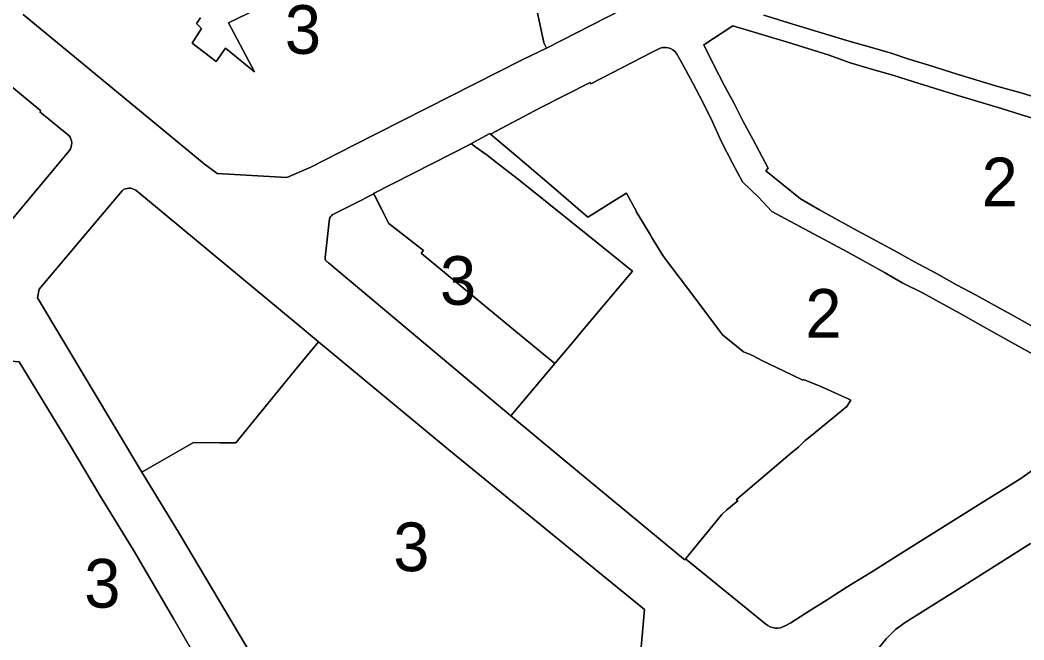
# Model space of a CAD drawing. Extents: x 598968 to 613553, y 4409678 to 4430833.
# Drawn here: x 607467.9 to 607715.2, y 4416082.8 to 4416235.4 of the extents above; entities that cross this region are included whole.
import ezdxf

# ---------------------------------------------------------------- set-up
doc = ezdxf.new("R2010")
doc.units = 0
for name, color, linetype in [('1', 7, 'Continuous'), ('ZONA 2. CARRERS DE CASES. Cases de trast', 7, 'Continuous'), ("ZONA 2_. CARRERS DE CASES. Afectades a ús d'aparcament", 7, 'Continuous'), ("ZONA 3. ILLES  D'EDIFICIS ENTRE MITGERES. EIXAMPLE.", 7, 'Continuous')]:
    doc.layers.add(name, color=color, linetype=linetype)

msp = doc.modelspace()

# ---------------------------------------------------------------- linework, layer by layer
at = {"layer": '1'}
for points in [[(607619.944, 4416239.9228), (607597.5985, 4416228.5216), (607591.5834, 4416225.5829), (607567.9956, 4416213.6341), (607550.1292, 4416204.571), (607539.5293, 4416199.2209), (607533.6794, 4416196.6108), (607516.4596, 4416197.5905), (607513.3096, 4416199.9804), (607468.71, 4416236.8092)], [(607721.2371, 4416215.4039), (607714.1772, 4416217.5738), (607708.7672, 4416219.0737), (607699.0273, 4416222.0135), (607691.7774, 4416224.2833), (607686.8275, 4416225.8132), (607682.4975, 4416227.2631), (607677.3976, 4416228.723), (607672.4376, 4416230.1329), (607667.2377, 4416231.7328), (607657.2478, 4416234.7326), (607651.1278, 4416236.6524)], [(607716.9073, 4416160.2145), (607712.1974, 4416162.8244), (607707.8974, 4416165.2243), (607703.4175, 4416167.6642), (607698.6075, 4416170.2441), (607693.6676, 4416172.9639), (607689.3276, 4416175.3138), (607686.6176, 4416176.7938), (607684.1576, 4416178.1337), (607678.9477, 4416180.9536), (607674.2277, 4416183.5435), (607669.4633, 4416186.1615), (607664.8593, 4416188.6726), (607660.1979, 4416191.4131), (607655.9179, 4416194.863), (607651.648, 4416198.2929), (607652.2368, 4416198.9129), (607648.478, 4416205.9028), (607646.068, 4416210.4327), (607643.848, 4416214.9026), (607641.468, 4416219.1925), (607638.758, 4416224.4924), (607636.318, 4416229.3423), (607643.5379, 4416234.0123), (607656.9978, 4416229.9626), (607667.2077, 4416226.7328), (607672.1676, 4416224.993), (607677.6176, 4416223.3331), (607682.9275, 4416221.8232), (607688.0675, 4416220.2333), (607693.0574, 4416218.6634), (607698.9573, 4416216.8335), (607709.6772, 4416213.6137), (607714.5844, 4416212.0789), (607726.6937, 4416208.4216)], [(607717.8874, 4416124.9849), (607714.4175, 4416122.5149), (607709.8276, 4416119.6449), (607705.3076, 4416116.8048), (607698.4977, 4416112.5847), (607691.7278, 4416108.3047), (607684.8479, 4416104.0046), (607678.128, 4416099.7745), (607671.4181, 4416095.6245), (607666.7193, 4416092.6325), (607662.3523, 4416089.8792), (607657.7883, 4416086.9943), (607656.4083, 4416086.2093), (607655.8294, 4416085.9363), (607655.2157, 4416085.7546), (607654.5814, 4416085.6686), (607653.9414, 4416085.6803), (607653.3107, 4416085.7893), (607652.704, 4416085.9931), (607652.1354, 4416086.2871), (607651.6183, 4416086.6642), (607647.1784, 4416090.2541), (607631.8185, 4416102.7037), (607631.9057, 4416102.8123), (607631.7881, 4416102.6694), (607631.6536, 4416102.5061), (607631.3761, 4416102.7355), (607605.725, 4416123.9398), (607589.2089, 4416137.5925), (607588.8489, 4416137.9325), (607543.8726, 4416175.6436), (607543.7433, 4416175.7506), (607543.5757, 4416175.8495), (607543.4249, 4416175.9723), (607543.2941, 4416176.1163), (607543.1864, 4416176.2782), (607543.1042, 4416176.4545), (607543.0493, 4416176.6412), (607543.0493, 4416176.9012), (607544.075, 4416185.7844), (607544.1393, 4416186.3411), (607544.1895, 4416186.5438), (607544.2686, 4416186.7371), (607544.3748, 4416186.9168), (607544.506, 4416187.0793), (607544.6593, 4416187.2211), (607544.8293, 4416187.4311), (607550.2042, 4416190.1528), (607555.0791, 4416192.6213), (607555.2659, 4416192.2488), (607558.7491, 4416185.3314), (607555.0291, 4416192.7313), (607579.0132, 4416204.9604), (607578.9988, 4416204.9715), (607583.6688, 4416207.4816), (607583.8455, 4416207.3309), (607596.0686, 4416213.7617), (607608.3484, 4416220.0219), (607608.5184, 4416219.7419), (607623.6382, 4416227.5121), (607625.6382, 4416228.5221), (607626.2668, 4416228.65), (607626.9081, 4416228.6674), (607627.5428, 4416228.5737), (607628.1517, 4416228.3717), (607628.7166, 4416228.0676), (607629.2205, 4416227.6705), (607629.6481, 4416227.1922), (607630.9181, 4416224.8822), (607633.6281, 4416219.8523), (607636.1281, 4416215.2024), (607638.4881, 4416210.3825), (607640.6881, 4416205.3926), (607643.418, 4416200.2027), (607645.908, 4416195.5728), (607649.848, 4416191.8029), (607653.118, 4416188.303), (607662.2779, 4416183.3433), (607671.7978, 4416178.2735), (607680.8277, 4416173.2037), (607685.3877, 4416170.6038), (607690.1876, 4416168.2439), (607699.4675, 4416163.1742), (607703.8675, 4416160.6943), (607708.522, 4416158.0906), (607718.0973, 4416152.7546)], [(607457.2101, 4416226.1392), (607473.03, 4416213.0596), (607472.812, 4416212.792), (607479.97, 4416206.9598), (607480.2482, 4416206.5532), (607480.4591, 4416206.108), (607480.5976, 4416205.6353), (607480.6603, 4416205.1466), (607480.6456, 4416204.6542), (607480.5538, 4416204.1702), (607480.3872, 4416203.7066), (607480.15, 4416203.2748), (607459.8054, 4416179.0508)], [(607531.6056, 4416067.8205), (607507.18, 4416108.8614), (607497.96, 4416124.0511), (607472.2502, 4416167.0001), (607472.6812, 4416169.1727), (607493.0625, 4416193.3947), (607493.4409, 4416193.647), (607493.8546, 4416193.8358), (607494.2931, 4416193.9563), (607494.7453, 4416194.0054), (607495.1995, 4416193.9818), (607495.6441, 4416193.8861), (607496.0678, 4416193.7209), (607496.4598, 4416193.4902), (607518.6343, 4416175.099), (607535.9547, 4416160.7338), (607541.4194, 4416156.2015), (607573.5541, 4416129.5773), (607608.0188, 4416101.3833), (607621.7387, 4416090.2436), (607620.8187, 4416080.0537)], [(607456.0406, 4416082.5608), (607456.6212, 4416082.8395), (607450.0006, 4416096.6305), (607449.4502, 4416096.3513), (607437.7707, 4416119.52), (607440.2806, 4416129.81), (607458.0203, 4416152.09), (607467.6803, 4416151.2402), (607480.0502, 4416131.0307), (607487.7302, 4416118.0409), (607495.8701, 4416104.8212), (607505.8101, 4416087.8316), (607519.47, 4416064.2221)], [(607720.2778, 4416011.0364), (607708.2079, 4416027.136), (607690.728, 4416050.7253), (607686.8089, 4416056.3927), (607679.4981, 4416066.9649), (607678.4081, 4416068.7349), (607677.9141, 4416070.3355), (607677.4081, 4416071.9748), (607677.3081, 4416074.9848), (607677.7081, 4416077.0548), (607677.8581, 4416077.7848), (607679.138, 4416080.3848), (607681.248, 4416083.0448), (607683.548, 4416085.3148), (607685.9179, 4416087.0348), (607691.6579, 4416090.6549), (607698.8973, 4416095.1959), (607716.8354, 4416106.5031)], [(607716.8354, 4416106.5031), (607698.8973, 4416095.1959), (607691.6579, 4416090.6549), (607685.9179, 4416087.0348), (607683.548, 4416085.3148), (607681.248, 4416083.0448), (607679.138, 4416080.3848), (607677.8581, 4416077.7848), (607677.7081, 4416077.0548), (607677.3081, 4416074.9848), (607677.4081, 4416071.9748), (607677.9141, 4416070.3355), (607678.4081, 4416068.7349), (607679.4981, 4416066.9649), (607686.8089, 4416056.3927), (607690.728, 4416050.7253), (607708.2079, 4416027.136), (607720.2778, 4416011.0364)]]:
    msp.add_lwpolyline(points, dxfattribs=at)
for points in [[(607583.8455, 4416207.3309), (607583.6688, 4416207.4816), (607578.9988, 4416204.9715), (607579.0132, 4416204.9604), (607579.0995, 4416204.8941), (607579.1034, 4416204.8962), (607579.8715, 4416204.3431), (607579.982, 4416204.2635), (607582.9838, 4416202.1016), (607585.6773, 4416200.0066), (607590.3697, 4416196.3567), (607593.5475, 4416193.885), (607607.7494, 4416182.4754), (607618.8184, 4416173.5826), (607606.9085, 4416159.4159), (607603.7901, 4416155.7067), (607599.6586, 4416150.7922), (607599.6622, 4416150.7891), (607588.8489, 4416137.9325), (607589.2089, 4416137.5925), (607605.725, 4416123.9398), (607631.3761, 4416102.7355), (607631.6536, 4416102.5061), (607631.7881, 4416102.6694), (607631.9057, 4416102.8123), (607640.7984, 4416113.6137), (607641.9933, 4416114.8254), (607644.7383, 4416116.9837), (607644.4306, 4416117.287), (607644.3683, 4416117.3484), (607648.7383, 4416121.0038), (607658.1281, 4416128.9938), (607659.6614, 4416130.2318), (607661.1981, 4416131.7539), (607663.798, 4416133.8539), (607671.5779, 4416140.2039), (607672.533, 4416141.8188), (607671.8901, 4416142.1101), (607665.218, 4416145.1338), (607660.888, 4416146.9237), (607660.778, 4416146.7237), (607660.7544, 4416146.7349), (607655.8381, 4416149.0736), (607650.7981, 4416151.5234), (607648.1627, 4416152.8523), (607646.1599, 4416153.7199), (607640.9582, 4416157.8732), (607634.3983, 4416166.663), (607626.3983, 4416177.1527), (607623.6626, 4416181.6573), (607623.1483, 4416182.6226), (607621.5187, 4416185.2771), (607619.6984, 4416188.2425), (607619.8087, 4416188.3061), (607617.3586, 4416192.6458), (607617.298, 4416192.7522), (607615.4359, 4416191.6562), (607607.9109, 4416186.9503), (607607.8186, 4416186.8923), (607598.8184, 4416194.5654), (607590.5506, 4416201.6144)], [(607599.6586, 4416150.7922), (607603.7901, 4416155.7067), (607606.9085, 4416159.4159), (607618.8184, 4416173.5826), (607607.7494, 4416182.4754), (607593.5475, 4416193.885), (607590.3697, 4416196.3567), (607585.6773, 4416200.0066), (607582.9838, 4416202.1016), (607579.982, 4416204.2635), (607579.8715, 4416204.3431), (607579.1034, 4416204.8962), (607579.0995, 4416204.8941), (607579.0132, 4416204.9604), (607555.0291, 4416192.7313), (607558.7491, 4416185.3314), (607567.309, 4416178.6516), (607566.7481, 4416177.9724), (607566.7892, 4416177.9385), (607589.102, 4416159.5108)], [(607541.4194, 4416156.2015), (607535.9547, 4416160.7338), (607518.6343, 4416175.099), (607496.4598, 4416193.4902), (607496.0678, 4416193.7209), (607495.6441, 4416193.8861), (607495.1995, 4416193.9818), (607494.7453, 4416194.0054), (607494.2931, 4416193.9563), (607493.8546, 4416193.8358), (607493.4409, 4416193.647), (607493.0625, 4416193.3947), (607472.6812, 4416169.1727), (607472.2502, 4416167.0001), (607497.96, 4416124.0511), (607508.3893, 4416130.0701), (607508.5302, 4416130.1506), (607510.6799, 4416131.3712), (607517.153, 4416131.3151), (607521.0498, 4416131.2814), (607530.8878, 4416143.3172), (607535.5506, 4416149.0216)]]:
    msp.add_lwpolyline(points, close=True, dxfattribs=at)
at = {"layer": 'ZONA 2. CARRERS DE CASES. Cases de trast'}
for points in [[(607593.0885, 4416247.9513), (607596.9085, 4416229.8816), (607597.0432, 4416229.6162), (607597.5985, 4416228.5216), (607619.944, 4416239.9228)], [(607651.1278, 4416236.6524), (607657.2478, 4416234.7326), (607667.2377, 4416231.7328), (607672.4376, 4416230.1329), (607677.3976, 4416228.723), (607682.4975, 4416227.2631), (607686.8275, 4416225.8132), (607691.7774, 4416224.2833), (607699.0273, 4416222.0135), (607708.7672, 4416219.0737), (607714.1772, 4416217.5738), (607721.2371, 4416215.4039)], [(607726.6937, 4416208.4216), (607714.5844, 4416212.0789), (607709.6772, 4416213.6137), (607698.9573, 4416216.8335), (607693.0574, 4416218.6634), (607688.0675, 4416220.2333), (607682.9275, 4416221.8232), (607677.6176, 4416223.3331), (607672.1676, 4416224.993), (607667.2077, 4416226.7328), (607656.9978, 4416229.9626), (607643.5379, 4416234.0123), (607636.318, 4416229.3423), (607638.758, 4416224.4924), (607641.468, 4416219.1925), (607643.848, 4416214.9026), (607646.068, 4416210.4327), (607648.478, 4416205.9028), (607652.2368, 4416198.9129), (607651.648, 4416198.2929), (607655.9179, 4416194.863), (607660.1979, 4416191.4131), (607664.8593, 4416188.6726), (607669.4633, 4416186.1615), (607674.2277, 4416183.5435), (607678.9477, 4416180.9536), (607684.1576, 4416178.1337), (607686.6176, 4416176.7938), (607689.3276, 4416175.3138), (607693.6676, 4416172.9639), (607698.6075, 4416170.2441), (607703.4175, 4416167.6642), (607707.8974, 4416165.2243), (607712.1974, 4416162.8244), (607716.9073, 4416160.2145)], [(607718.0973, 4416152.7546), (607708.522, 4416158.0906), (607703.8675, 4416160.6943), (607699.4675, 4416163.1742), (607690.1876, 4416168.2439), (607685.3877, 4416170.6038), (607680.8277, 4416173.2037), (607671.7978, 4416178.2735), (607662.2779, 4416183.3433), (607653.118, 4416188.303), (607649.848, 4416191.8029), (607645.908, 4416195.5728), (607643.418, 4416200.2027), (607640.6881, 4416205.3926), (607638.4881, 4416210.3825), (607636.1281, 4416215.2024), (607633.6281, 4416219.8523), (607630.9181, 4416224.8822), (607629.6481, 4416227.1922), (607629.2205, 4416227.6705), (607628.7166, 4416228.0676), (607628.1517, 4416228.3717), (607627.5428, 4416228.5737), (607626.9081, 4416228.6674), (607626.2668, 4416228.65), (607625.6382, 4416228.5221), (607623.6382, 4416227.5121), (607608.5184, 4416219.7419), (607608.3484, 4416220.0219), (607596.0686, 4416213.7617), (607583.8455, 4416207.3309), (607590.5506, 4416201.6144), (607598.8184, 4416194.5654), (607607.8186, 4416186.8923), (607607.9109, 4416186.9503), (607615.4359, 4416191.6562), (607617.298, 4416192.7522), (607617.3586, 4416192.6458), (607619.8087, 4416188.3061), (607619.6984, 4416188.2425), (607621.5187, 4416185.2771), (607623.1483, 4416182.6226), (607623.6626, 4416181.6573), (607626.3983, 4416177.1527), (607634.3983, 4416166.663), (607640.9582, 4416157.8732), (607646.1599, 4416153.7199), (607648.1627, 4416152.8523), (607650.7981, 4416151.5234), (607655.8381, 4416149.0736), (607660.7544, 4416146.7349), (607660.778, 4416146.7237), (607660.888, 4416146.9237), (607665.218, 4416145.1338), (607671.8901, 4416142.1101), (607672.533, 4416141.8188), (607671.5779, 4416140.2039), (607663.798, 4416133.8539), (607661.1981, 4416131.7539), (607659.6614, 4416130.2318), (607658.1281, 4416128.9938), (607648.7383, 4416121.0038), (607644.3683, 4416117.3484), (607644.4306, 4416117.287), (607644.7383, 4416116.9837), (607641.9933, 4416114.8254), (607640.7984, 4416113.6137), (607631.9057, 4416102.8123), (607631.8185, 4416102.7037), (607647.1784, 4416090.2541), (607651.6183, 4416086.6642), (607652.1354, 4416086.2871), (607652.704, 4416085.9931), (607653.3107, 4416085.7893), (607653.9414, 4416085.6803), (607654.5814, 4416085.6686), (607655.2157, 4416085.7546), (607655.8294, 4416085.9363), (607656.4083, 4416086.2093), (607657.7883, 4416086.9943), (607662.3523, 4416089.8792), (607666.7193, 4416092.6325), (607671.4181, 4416095.6245), (607678.128, 4416099.7745), (607684.8479, 4416104.0046), (607691.7278, 4416108.3047), (607698.4977, 4416112.5847), (607705.3076, 4416116.8048), (607709.8276, 4416119.6449), (607714.4175, 4416122.5149), (607717.8874, 4416124.9849)]]:
    msp.add_lwpolyline(points, dxfattribs=at)
at = {"layer": "ZONA 2_. CARRERS DE CASES. Afectades a ús d'aparcament"}
msp.add_lwpolyline([(607512.3695, 4416235.96), (607511.3895, 4416234.59), (607512.5895, 4416233.33), (607510.3495, 4416229.75), (607516.2795, 4416225.2102), (607518.5494, 4416228.4902), (607525.6594, 4416222.7004), (607519.2494, 4416234.7101), (607530.8793, 4416240.3403)], dxfattribs=at)
at = {"layer": "ZONA 3. ILLES  D'EDIFICIS ENTRE MITGERES. EIXAMPLE."}
for points in [[(607468.71, 4416236.8092), (607513.3096, 4416199.9804), (607516.4596, 4416197.5905), (607533.6794, 4416196.6108), (607539.5293, 4416199.2209), (607550.1292, 4416204.571), (607567.9956, 4416213.6341), (607591.5834, 4416225.5829), (607597.5985, 4416228.5216), (607597.0432, 4416229.6162), (607596.9085, 4416229.8816), (607593.0885, 4416247.9513)], [(607530.8793, 4416240.3403), (607519.2494, 4416234.7101), (607525.6594, 4416222.7004), (607518.5494, 4416228.4902), (607516.2795, 4416225.2102), (607510.3495, 4416229.75), (607512.5895, 4416233.33), (607511.3895, 4416234.59), (607512.3695, 4416235.96)], [(607459.8054, 4416179.0508), (607480.15, 4416203.2748), (607480.3872, 4416203.7066), (607480.5538, 4416204.1702), (607480.6456, 4416204.6542), (607480.6603, 4416205.1466), (607480.5976, 4416205.6353), (607480.4591, 4416206.108), (607480.2482, 4416206.5532), (607479.97, 4416206.9598), (607472.812, 4416212.792), (607473.03, 4416213.0596), (607457.2101, 4416226.1392)], [(607620.8187, 4416080.0537), (607621.7387, 4416090.2436), (607608.0188, 4416101.3833), (607573.5541, 4416129.5773), (607541.4194, 4416156.2015), (607535.5506, 4416149.0216), (607530.8878, 4416143.3172), (607521.0498, 4416131.2814), (607517.153, 4416131.3151), (607510.6799, 4416131.3712), (607508.5302, 4416130.1506), (607508.3893, 4416130.0701), (607497.96, 4416124.0511), (607507.18, 4416108.8614), (607531.6056, 4416067.8205)], [(607519.47, 4416064.2221), (607505.8101, 4416087.8316), (607495.8701, 4416104.8212), (607487.7302, 4416118.0409), (607480.0502, 4416131.0307), (607467.6803, 4416151.2402), (607458.0203, 4416152.09), (607440.2806, 4416129.81), (607437.7707, 4416119.52), (607449.4502, 4416096.3513), (607450.0006, 4416096.6305), (607456.6212, 4416082.8395), (607456.0406, 4416082.5608)]]:
    msp.add_lwpolyline(points, dxfattribs=at)
msp.add_lwpolyline([(607558.7491, 4416185.3314), (607555.2659, 4416192.2488), (607555.0791, 4416192.6213), (607550.2042, 4416190.1528), (607544.8293, 4416187.4311), (607544.6593, 4416187.2211), (607544.506, 4416187.0793), (607544.3748, 4416186.9168), (607544.2686, 4416186.7371), (607544.1895, 4416186.5438), (607544.1393, 4416186.3411), (607544.075, 4416185.7844), (607543.0493, 4416176.9012), (607543.0493, 4416176.6412), (607543.1042, 4416176.4545), (607543.1864, 4416176.2782), (607543.2941, 4416176.1163), (607543.4249, 4416175.9723), (607543.5757, 4416175.8495), (607543.7433, 4416175.7506), (607543.8726, 4416175.6436), (607588.8489, 4416137.9325), (607599.6622, 4416150.7891), (607599.6586, 4416150.7922), (607589.102, 4416159.5108), (607566.7892, 4416177.9385), (607566.7481, 4416177.9724), (607567.309, 4416178.6516)], close=True, dxfattribs=at)

# ---------------------------------------------------------------- texts
at = {"layer": 'ZONA 2. CARRERS DE CASES. Cases de trast'}
for p in [(607704.7673, 4416189.5387), (607661.3513, 4416157.168)]:
    msp.add_text('2', height=12, dxfattribs=at).set_placement(p)
at = {"layer": "ZONA 3. ILLES  D'EDIFICIS ENTRE MITGERES. EIXAMPLE."}
for p in [(607533.1543, 4416227.0908), (607571.3558, 4416165.2769), (607559.8493, 4416099.6782), (607483.7403, 4416090.701)]:
    msp.add_text('3', height=12, dxfattribs=at).set_placement(p)

doc.saveas('drawing.dxf')
